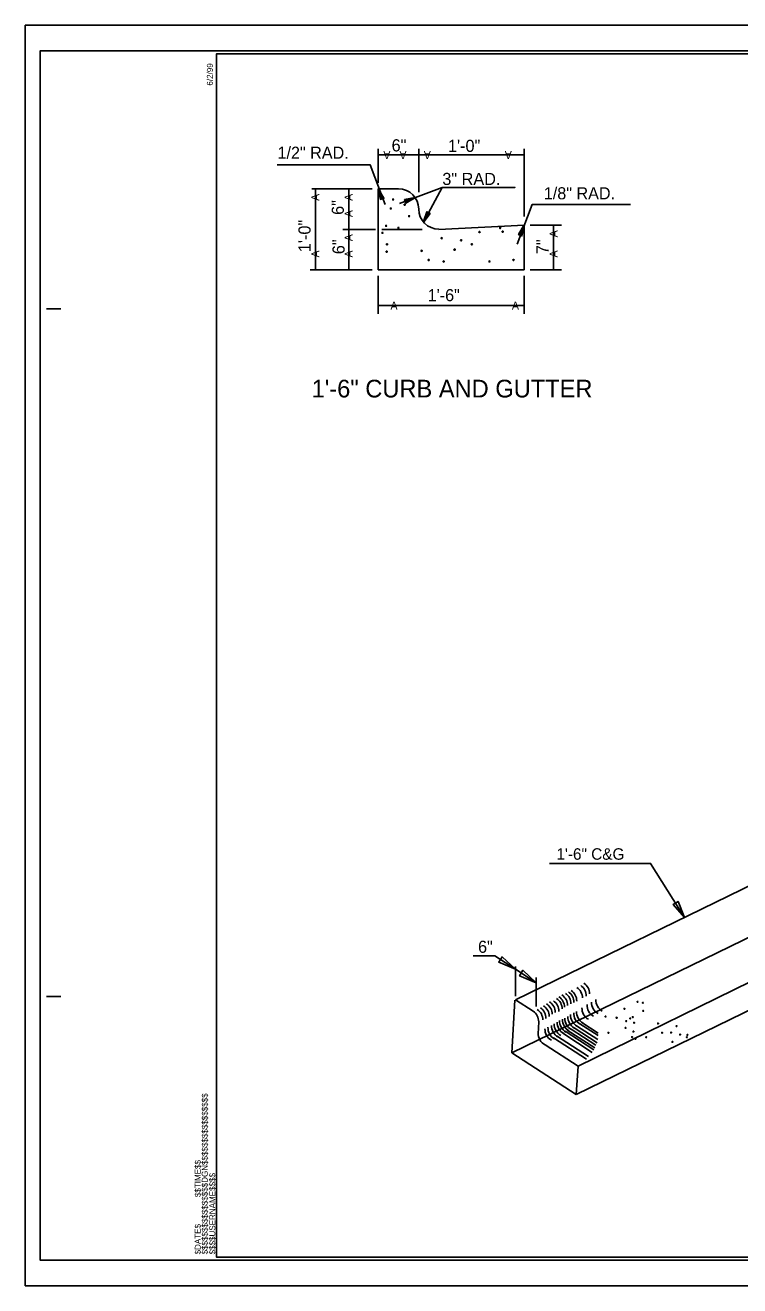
# Model space of a CAD drawing. Extents: x 1252282 to 1252460, y 733735 to 733845.
# Drawn here: x 1252282.2 to 1252344.6, y 733734.5 to 733844.5 of the extents above; entities that cross this region are included whole.
import ezdxf

# ---------------------------------------------------------------- set-up
doc = ezdxf.new("R2010")
doc.units = 0
for name, color, linetype in [('Default', 7, 'Continuous'), ('Old_Level_2', 7, 'Continuous'), ('Old_Level_23', 7, 'Continuous'), ('Old_Level_3', 7, 'Continuous'), ('Sheet Block System Information CELL', 7, 'Continuous'), ('Sheet Cutting Line CELL', 7, 'Continuous'), ('Sheet Plot Border Inside CELL', 7, 'Continuous'), ('Sheet Plot Border Outside CELL', 7, 'Continuous'), ('Sheet Typical CELL', 7, 'Continuous')]:
    doc.layers.add(name, color=color, linetype=linetype)

msp = doc.modelspace()

# ---------------------------------------------------------------- linework, layer by layer
at = {"layer": 'Default'}
for p, q in [((1252351.16, 733772.21), (1252325, 733759.45)), ((1252350.92, 733767.63), (1252324.68, 733754.83)), ((1252356.6, 733766.46), (1252330.45, 733753.68)), ((1252330.28, 733751.19), (1252356.52, 733763.99)), ((1252324.98, 733759.78), (1252324.98, 733762.37)), ((1252324.98, 733762.12), (1252326.79, 733760.94)), ((1252326.79, 733758.87), (1252326.79, 733761.41)), ((1252324.68, 733754.83), (1252324.93, 733759.43)), ((1252325, 733759.45), (1252326.53, 733758.46)), ((1252327.01, 733757.55), (1252326.96, 733756.5)), ((1252330.6, 733757.36), (1252332.2, 733756.33)), ((1252330.77, 733757.48), (1252332.21, 733756.54)), ((1252328.3, 733756.14), (1252331.18, 733754.27)), ((1252328.57, 733756.31), (1252331.37, 733754.5)), ((1252329.11, 733756.55), (1252331.69, 733754.87)), ((1252329.32, 733756.72), (1252331.82, 733755.1)), ((1252329.51, 733756.82), (1252331.9, 733755.26)), ((1252329.85, 733756.89), (1252332.01, 733755.49)), ((1252330.1, 733757.02), (1252332.12, 733755.71)), ((1252330.31, 733757.19), (1252332.17, 733755.99)), ((1252327.58, 733755.54), (1252330.45, 733753.68)), ((1252330.28, 733751.19), (1252324.68, 733754.83)), ((1252330.45, 733753.68), (1252330.28, 733751.19))]:
    msp.add_line(p, q, dxfattribs=at)
for points in [[(1252327.97, 733771.36), (1252336.78, 733771.36), (1252339.75, 733766.64)], [(1252321.29, 733763.3), (1252323.17, 733763.3), (1252324.98, 733762.12)]]:
    msp.add_lwpolyline(points, dxfattribs=at)
msp.add_lwpolyline([(1252339.75, 733766.64), (1252338.74, 733767.76), (1252339.18, 733768.04)], close=True, dxfattribs=at)
for centre in [(1252334.5, 733758.68), (1252335.65, 733759.29), (1252336.11, 733759.2), (1252336.14, 733758.49), (1252332.85, 733757.99), (1252333.82, 733757.89), (1252334.66, 733757.6), (1252335, 733757.83), (1252335.22, 733757.95), (1252335.34, 733757.45), (1252337.43, 733757.39), (1252339.05, 733757.16), (1252333.1, 733756.58), (1252334.6, 733757), (1252335.16, 733756.21), (1252335.28, 733756.69), (1252335.45, 733756.06), (1252336.4, 733756.19), (1252337.78, 733756.58), (1252338.57, 733756.6), (1252339.36, 733756.42), (1252339.95, 733756.19), (1252340, 733756.4), (1252338.69, 733755.78)]:
    msp.add_circle(centre, 0.0425, dxfattribs=at)
for centre, start, end in [((1252329.74, 733759.63), 359.5174, 56.4255), ((1252330.08, 733759.79), 359.5174, 56.4255), ((1252330.36, 733759.99), 359.5174, 56.4255), ((1252327.97, 733758.67), 359.5174, 56.4255), ((1252328.17, 733758.82), 359.5174, 56.4255), ((1252328.44, 733758.97), 359.5174, 56.4255), ((1252328.74, 733759.11), 359.5174, 56.4255), ((1252329, 733759.24), 359.5174, 56.4255), ((1252329.24, 733759.36), 359.5174, 56.4255), ((1252333.09, 733759.43), 177.4498, 241.2122), ((1252325.92, 733757.55), 359.5174, 56.4255), ((1252326.28, 733757.71), 359.5174, 56.4255), ((1252326.56, 733757.84), 359.5174, 56.4255), ((1252326.84, 733758.02), 359.5174, 56.4255), ((1252327.1, 733758.2), 359.5174, 56.4255), ((1252327.36, 733758.37), 359.5174, 56.4255), ((1252327.69, 733758.46), 359.5174, 56.4255), ((1252331.16, 733758.28), 177.4498, 241.2122), ((1252331.4, 733758.39), 177.4498, 241.2122), ((1252331.88, 733758.71), 177.4498, 241.2122), ((1252332.32, 733758.99), 177.4498, 241.2122), ((1252332.72, 733759.21), 177.4498, 241.2122), ((1252329.22, 733757.17), 177.4498, 241.2122), ((1252329.46, 733757.31), 177.4498, 241.2122), ((1252329.72, 733757.47), 177.4498, 241.2122), ((1252329.92, 733757.6), 177.4498, 241.2122), ((1252330.18, 733757.71), 177.4498, 241.2122), ((1252330.39, 733757.82), 177.4498, 241.2122), ((1252330.65, 733757.95), 177.4498, 241.2122), ((1252330.88, 733758.12), 177.4498, 241.2122), ((1252328.05, 733756.52), 177.4498, 244.614), ((1252328.65, 733756.89), 177.4498, 241.2122), ((1252328.91, 733757.01), 177.4498, 241.2122)]:
    msp.add_arc(centre, 1.09, start, end, dxfattribs=at)
at = {"layer": 'Old_Level_2'}
for p, q in [((1252313.01, 733830.23), (1252313.5, 733829.41)), ((1252313.01, 733830.23), (1252313.19, 733829.29)), ((1252313.19, 733829.29), (1252313.5, 733829.41)), ((1252316.24, 733829.46), (1252315.3, 733829.28)), ((1252315.3, 733829.28), (1252315.42, 733828.96)), ((1252316.24, 733829.46), (1252315.42, 733828.96)), ((1252316.95, 733827.31), (1252317.25, 733828.22)), ((1252316.95, 733827.31), (1252317.54, 733828.06)), ((1252317.54, 733828.06), (1252317.25, 733828.22)), ((1252325.73, 733827.05), (1252325.25, 733826.24)), ((1252325.73, 733827.05), (1252325.55, 733826.11)), ((1252325.55, 733826.11), (1252325.25, 733826.24))]:
    msp.add_line(p, q, dxfattribs=at)
for points in [[(1252313.35, 733829.36), (1252313.02, 733830.2), (1252313.27, 733829.32), (1252313.02, 733830.21), (1252313.44, 733829.38), (1252313.03, 733830.2), (1252313.39, 733829.38), (1252313.03, 733830.2), (1252313.31, 733829.34), (1252313.03, 733830.2), (1252313.23, 733829.31), (1252313.03, 733830.2), (1252313.21, 733829.3), (1252313.03, 733830.2), (1252313.33, 733829.34), (1252313.03, 733830.18), (1252313.47, 733829.39), (1252313.03, 733830.19), (1252313.42, 733829.38), (1252313.06, 733830.12), (1252313.38, 733829.36), (1252313.03, 733830.19), (1252313.37, 733829.36), (1252313.03, 733830.18), (1252313.26, 733829.32), (1252313.04, 733830.17), (1252313.29, 733829.33), (1252313.03, 733830.17), (1252313.45, 733829.39), (1252313.03, 733830.19), (1252313.5, 733829.41), (1252313.03, 733830.17), (1252313.5, 733829.41), (1252313.04, 733830.19), (1252313.18, 733829.96), (1252313.05, 733830.17), (1252313.45, 733829.38), (1252313.03, 733830.17), (1252313.2, 733829.3), (1252313.03, 733830.15), (1252313.19, 733829.3), (1252313.02, 733830.21), (1252313.24, 733829.31), (1252313.05, 733830.16), (1252313.32, 733829.34), (1252313.04, 733830.17), (1252313.3, 733829.34), (1252313.05, 733830.15), (1252313.41, 733829.38), (1252313.03, 733830.19), (1252313.48, 733829.41), (1252313.03, 733830.19), (1252313.22, 733829.3), (1252313.03, 733830.19), (1252313.26, 733829.31), (1252313.03, 733830.17), (1252313.34, 733829.35), (1252313.03, 733830.17), (1252313.38, 733829.36), (1252313.03, 733830.18), (1252313.4, 733829.38), (1252313.03, 733830.18), (1252313.43, 733829.38), (1252313.03, 733830.19), (1252313.46, 733829.41), (1252313.03, 733830.19), (1252313.45, 733829.38), (1252313.03, 733830.19), (1252313.48, 733829.41), (1252313.03, 733830.18), (1252313.32, 733829.34), (1252313.03, 733830.2), (1252313.35, 733829.36), (1252313.03, 733830.2), (1252313.29, 733829.34), (1252313.03, 733830.19), (1252313.28, 733829.32), (1252313.03, 733830.17), (1252313.25, 733829.31), (1252313.03, 733830.19), (1252313.22, 733829.3), (1252313.06, 733830.03), (1252313.21, 733829.3), (1252313.11, 733829.81), (1252313.2, 733829.3), (1252313.15, 733829.75), (1252313.27, 733829.32), (1252313.16, 733829.7), (1252313.38, 733829.36), (1252313.13, 733829.94), (1252313.4, 733829.38), (1252313.15, 733829.87), (1252313.39, 733829.36), (1252313.19, 733829.79), (1252313.35, 733829.35), (1252313.2, 733829.71), (1252313.34, 733829.35), (1252313.13, 733829.97), (1252313.43, 733829.38), (1252313.19, 733829.85), (1252313.43, 733829.38)], [(1252315.37, 733829.11), (1252316.21, 733829.45), (1252315.34, 733829.19), (1252316.23, 733829.45), (1252315.4, 733829.02), (1252316.21, 733829.44), (1252315.38, 733829.08), (1252316.21, 733829.44), (1252315.35, 733829.15), (1252316.21, 733829.44), (1252315.32, 733829.23), (1252316.21, 733829.44), (1252315.31, 733829.25), (1252316.21, 733829.44), (1252315.35, 733829.14), (1252316.18, 733829.44), (1252315.41, 733828.98), (1252316.2, 733829.43), (1252315.39, 733829.04), (1252316.13, 733829.41), (1252315.38, 733829.09), (1252316.2, 733829.43), (1252315.37, 733829.1), (1252316.18, 733829.43), (1252315.34, 733829.2), (1252316.18, 733829.43), (1252315.34, 733829.17), (1252316.18, 733829.43), (1252315.41, 733829.01), (1252316.2, 733829.44), (1252315.42, 733828.97), (1252316.18, 733829.43), (1252315.42, 733828.97), (1252316.2, 733829.43), (1252315.97, 733829.29), (1252316.18, 733829.41), (1252315.4, 733829.02), (1252316.18, 733829.43), (1252315.31, 733829.27), (1252316.16, 733829.43), (1252315.31, 733829.27), (1252316.23, 733829.45), (1252315.33, 733829.23), (1252316.17, 733829.41), (1252315.35, 733829.14), (1252316.18, 733829.43), (1252315.35, 733829.16), (1252316.16, 733829.41), (1252315.39, 733829.06), (1252316.2, 733829.43), (1252315.42, 733828.98), (1252316.2, 733829.43), (1252315.31, 733829.23), (1252316.2, 733829.43), (1252315.33, 733829.2), (1252316.18, 733829.43), (1252315.36, 733829.12), (1252316.18, 733829.43), (1252315.38, 733829.09), (1252316.18, 733829.43), (1252315.39, 733829.06), (1252316.18, 733829.43), (1252315.4, 733829.04), (1252316.2, 733829.44), (1252315.41, 733829), (1252316.2, 733829.43), (1252315.4, 733829.01), (1252316.2, 733829.43), (1252315.41, 733828.98), (1252316.18, 733829.43), (1252315.35, 733829.15), (1252316.21, 733829.44), (1252315.37, 733829.11), (1252316.21, 733829.44), (1252315.35, 733829.17), (1252316.2, 733829.44), (1252315.34, 733829.18), (1252316.18, 733829.43), (1252315.33, 733829.22), (1252316.2, 733829.44), (1252315.31, 733829.23), (1252316.04, 733829.41), (1252315.31, 733829.26), (1252315.81, 733829.35), (1252315.31, 733829.27), (1252315.76, 733829.32), (1252315.34, 733829.19), (1252315.72, 733829.3), (1252315.38, 733829.08), (1252315.95, 733829.33), (1252315.38, 733829.06), (1252315.88, 733829.31), (1252315.38, 733829.08), (1252315.8, 733829.28), (1252315.36, 733829.11), (1252315.73, 733829.27), (1252315.36, 733829.13), (1252315.99, 733829.33), (1252315.39, 733829.04), (1252315.86, 733829.27), (1252315.4, 733829.02)], [(1252317.39, 733828.14), (1252316.96, 733827.33), (1252317.45, 733828.11), (1252316.96, 733827.33), (1252317.31, 733828.19), (1252316.96, 733827.34), (1252317.34, 733828.16), (1252316.96, 733827.33), (1252317.42, 733828.12), (1252316.96, 733827.33), (1252317.5, 733828.08), (1252316.96, 733827.33), (1252317.51, 733828.07), (1252316.96, 733827.34), (1252317.41, 733828.14), (1252316.97, 733827.36), (1252317.27, 733828.2), (1252316.97, 733827.36), (1252317.32, 733828.18), (1252317, 733827.42), (1252317.36, 733828.16), (1252316.97, 733827.36), (1252317.37, 733828.14), (1252316.98, 733827.36), (1252317.47, 733828.09), (1252316.98, 733827.37), (1252317.45, 733828.11), (1252316.99, 733827.37), (1252317.29, 733828.2), (1252316.97, 733827.35), (1252317.26, 733828.21), (1252316.98, 733827.37), (1252317.26, 733828.22), (1252316.96, 733827.36), (1252317.05, 733827.62), (1252316.98, 733827.38), (1252317.31, 733828.19), (1252316.99, 733827.37), (1252317.53, 733828.06), (1252317, 733827.37), (1252317.53, 733828.06), (1252316.96, 733827.33), (1252317.48, 733828.08), (1252316.99, 733827.38), (1252317.41, 733828.12), (1252316.99, 733827.37), (1252317.43, 733828.12), (1252316.99, 733827.4), (1252317.33, 733828.17), (1252316.96, 733827.35), (1252317.26, 733828.21), (1252316.96, 733827.35), (1252317.51, 733828.07), (1252316.97, 733827.36), (1252317.47, 733828.09), (1252316.98, 733827.37), (1252317.39, 733828.14), (1252316.98, 733827.37), (1252317.37, 733828.16), (1252316.98, 733827.36), (1252317.34, 733828.17), (1252316.98, 733827.36), (1252317.32, 733828.18), (1252316.98, 733827.35), (1252317.28, 733828.2), (1252316.97, 733827.36), (1252317.3, 733828.2), (1252316.96, 733827.35), (1252317.26, 733828.21), (1252316.98, 733827.36), (1252317.41, 733828.12), (1252316.96, 733827.33), (1252317.38, 733828.14), (1252316.96, 733827.34), (1252317.44, 733828.11), (1252316.96, 733827.34), (1252317.45, 733828.11), (1252316.98, 733827.37), (1252317.48, 733828.09), (1252316.97, 733827.35), (1252317.51, 733828.07), (1252317.06, 733827.49), (1252317.52, 733828.07), (1252317.2, 733827.67), (1252317.53, 733828.07), (1252317.22, 733827.73), (1252317.47, 733828.09), (1252317.25, 733827.77), (1252317.35, 733828.16), (1252317.08, 733827.58), (1252317.34, 733828.17), (1252317.13, 733827.66), (1252317.35, 733828.16), (1252317.17, 733827.73), (1252317.39, 733828.14), (1252317.22, 733827.8), (1252317.4, 733828.14), (1252317.06, 733827.56), (1252317.32, 733828.19), (1252317.11, 733827.69), (1252317.31, 733828.19)], [(1252325.39, 733826.18), (1252325.73, 733827.03), (1252325.47, 733826.14), (1252325.73, 733827.03), (1252325.31, 733826.21), (1252325.72, 733827.02), (1252325.35, 733826.19), (1252325.72, 733827.03), (1252325.44, 733826.16), (1252325.72, 733827.03), (1252325.51, 733826.13), (1252325.72, 733827.03), (1252325.54, 733826.12), (1252325.72, 733827.03), (1252325.41, 733826.17), (1252325.72, 733827), (1252325.28, 733826.21), (1252325.71, 733827.01), (1252325.32, 733826.21), (1252325.69, 733826.95), (1252325.36, 733826.18), (1252325.71, 733827.01), (1252325.38, 733826.18), (1252325.71, 733827), (1252325.48, 733826.14), (1252325.7, 733826.99), (1252325.46, 733826.15), (1252325.71, 733826.99), (1252325.29, 733826.21), (1252325.72, 733827.01), (1252325.25, 733826.24), (1252325.71, 733827), (1252325.25, 733826.24), (1252325.7, 733827.01), (1252325.57, 733826.77), (1252325.7, 733826.99), (1252325.3, 733826.21), (1252325.71, 733826.99), (1252325.54, 733826.12), (1252325.71, 733826.97), (1252325.55, 733826.12), (1252325.73, 733827.03), (1252325.5, 733826.14), (1252325.7, 733826.98), (1252325.42, 733826.17), (1252325.7, 733826.99), (1252325.44, 733826.16), (1252325.7, 733826.97), (1252325.34, 733826.21), (1252325.71, 733827.01), (1252325.26, 733826.24), (1252325.71, 733827.01), (1252325.52, 733826.12), (1252325.71, 733827.01), (1252325.47, 733826.14), (1252325.71, 733826.99), (1252325.4, 733826.17), (1252325.71, 733827), (1252325.37, 733826.18), (1252325.71, 733827), (1252325.34, 733826.19), (1252325.71, 733827), (1252325.31, 733826.21), (1252325.72, 733827.01), (1252325.28, 733826.23), (1252325.71, 733827.01), (1252325.29, 733826.21), (1252325.71, 733827.01), (1252325.26, 733826.23), (1252325.71, 733827), (1252325.42, 733826.17), (1252325.72, 733827.03), (1252325.39, 733826.18), (1252325.72, 733827.02), (1252325.45, 733826.16), (1252325.72, 733827.01), (1252325.47, 733826.14), (1252325.71, 733827), (1252325.5, 733826.14), (1252325.72, 733827.01), (1252325.52, 733826.12), (1252325.68, 733826.85), (1252325.54, 733826.12), (1252325.63, 733826.63), (1252325.54, 733826.12), (1252325.6, 733826.56), (1252325.47, 733826.14), (1252325.58, 733826.52), (1252325.36, 733826.18), (1252325.61, 733826.77), (1252325.34, 733826.19), (1252325.59, 733826.69), (1252325.35, 733826.18), (1252325.56, 733826.62), (1252325.39, 733826.17), (1252325.54, 733826.53), (1252325.41, 733826.17), (1252325.61, 733826.8), (1252325.31, 733826.21), (1252325.55, 733826.68), (1252325.31, 733826.21)]]:
    msp.add_lwpolyline(points, dxfattribs=at)
for points in [[(1252324.98, 733762.12), (1252323.52, 733762.74), (1252323.82, 733763.2)], [(1252326.79, 733760.94), (1252325.34, 733761.56), (1252325.64, 733762.03)]]:
    msp.add_lwpolyline(points, close=True, dxfattribs=at)
at = {"layer": 'Old_Level_23'}
for p, q in [((1252313.01, 733830.76), (1252313.01, 733833.71)), ((1252316.55, 733833.18), (1252313.01, 733833.18)), ((1252316.55, 733829.92), (1252316.55, 733833.71)), ((1252325.73, 733833.18), (1252316.55, 733833.18)), ((1252325.73, 733827.82), (1252325.73, 733833.71)), ((1252312.48, 733830.23), (1252307.21, 733830.23)), ((1252307.53, 733823.17), (1252307.53, 733830.23)), ((1252310.44, 733826.69), (1252310.44, 733830.23)), ((1252312.77, 733826.69), (1252309.9, 733826.69)), ((1252310.44, 733823.17), (1252310.44, 733826.69)), ((1252316.85, 733826.69), (1252313.32, 733826.69)), ((1252326.26, 733827.05), (1252328.99, 733827.05)), ((1252328.31, 733823.17), (1252328.31, 733827.05)), ((1252312.48, 733823.17), (1252307.05, 733823.17)), ((1252313.01, 733822.64), (1252313.01, 733819.31)), ((1252325.73, 733822.64), (1252325.73, 733819.31)), ((1252326.26, 733823.17), (1252328.99, 733823.17)), ((1252313.01, 733820.03), (1252325.73, 733820.03))]:
    msp.add_line(p, q, dxfattribs=at)
for points in [[(1252313.6, 733828.85), (1252312.29, 733832.32), (1252304.19, 733832.32)], [(1252316.95, 733827.31), (1252318.58, 733830.35), (1252324.94, 733830.35), (1252318.58, 733830.35), (1252314.86, 733828.94)], [(1252325.12, 733825.39), (1252326.43, 733828.85), (1252335.02, 733828.85)]]:
    msp.add_lwpolyline(points, dxfattribs=at)
at = {"layer": 'Old_Level_3'}
msp.add_lwpolyline([(1252314.78, 733830.23), (1252313.01, 733830.23), (1252313.01, 733823.17), (1252325.73, 733823.17), (1252325.73, 733827.05), (1252318.3, 733826.69)], dxfattribs=at)
for centre, radius in [((1252314.31, 733829.3), 0.0517), ((1252315.31, 733828.84), 0.0517), ((1252314.1, 733828.51), 0.0517), ((1252315.7, 733827.84), 0.0517), ((1252313.69, 733826.99), 0.0517), ((1252314.77, 733826.82), 0.0548), ((1252321.84, 733826.46), 0.0517), ((1252323.65, 733826.8), 0.0517), ((1252323.87, 733826.49), 0.0517), ((1252313.38, 733826.38), 0.0517), ((1252313.77, 733825.38), 0.0517), ((1252318.54, 733825.92), 0.0517), ((1252320.24, 733825.73), 0.0561), ((1252321.17, 733825.38), 0.0517), ((1252313.74, 733824.74), 0.0517), ((1252316.8, 733824.81), 0.0517), ((1252319.67, 733824.92), 0.0556), ((1252317.4, 733824.01), 0.0517), ((1252318.71, 733823.88), 0.0517), ((1252322.72, 733823.89), 0.0517), ((1252324.81, 733824.01), 0.0517)]:
    msp.add_circle(centre, radius, dxfattribs=at)
for centre, start, end in [((1252314.78, 733828.46), 0, 90), ((1252318.3, 733828.46), 180, 270)]:
    msp.add_arc(centre, 1.76, start, end, dxfattribs=at)
at = {"layer": 'Sheet Block System Information CELL'}
msp.add_line((1252298.88, 733737), (1252298.88, 733737), dxfattribs=at)
msp.add_line((1252298.88, 733737), (1252298.88, 733737), dxfattribs=at)
at = {"layer": 'Sheet Cutting Line CELL'}
for p, q in [((1252450.58, 733844.5), (1252282.18, 733844.5)), ((1252282.18, 733844.5), (1252282.18, 733734.5)), ((1252282.18, 733734.5), (1252450.58, 733734.5))]:
    msp.add_line(p, q, dxfattribs=at)
at = {"layer": 'Sheet Plot Border Inside CELL'}
msp.add_lwpolyline([(1252450.13, 733842.26), (1252283.48, 733842.26), (1252283.48, 733736.75), (1252450.13, 733736.75)], close=True, dxfattribs=at)
at = {"layer": 'Sheet Plot Border Outside CELL'}
msp.add_lwpolyline([(1252450.58, 733844.5), (1252282.18, 733844.5), (1252282.18, 733734.5), (1252450.58, 733734.5)], close=True, dxfattribs=at)
at = {"layer": 'Sheet Typical CELL'}
for p, q in [((1252284.03, 733819.75), (1252285.28, 733819.75)), ((1252284.03, 733759.75), (1252285.28, 733759.75)), ((1252298.88, 733737), (1252298.88, 733737)), ((1252298.88, 733737), (1252298.88, 733737)), ((1252298.88, 733737), (1252298.88, 733737)), ((1252298.88, 733737), (1252298.88, 733737)), ((1252298.88, 733737), (1252298.88, 733737)), ((1252298.88, 733737), (1252298.88, 733737))]:
    msp.add_line(p, q, dxfattribs=at)
msp.add_lwpolyline([(1252448.88, 733842), (1252298.88, 733842), (1252298.88, 733737), (1252448.88, 733737)], close=True, dxfattribs=at)
msp.add_lwpolyline([(1252302.63, 733737), (1252302.63, 733737)], dxfattribs=at)

# ---------------------------------------------------------------- texts
at = {"layer": 'Default'}
for s, height, p in [('1\'-6" C&G', 1.001, (1252328.56, 733771.68)), ('6"', 1.054, (1252321.72, 733763.56))]:
    msp.add_text(s, height=height, dxfattribs=at).set_placement(p)
at = {"layer": 'Old_Level_23'}
for s, height, p in [('6"', 1.06, (1252314.17, 733833.49)), ('1\'-0"', 1.06, (1252319.09, 733833.45)), ('1/2" RAD.', 1.054, (1252304.21, 733832.85)), ('3" RAD.', 1.06, (1252318.6, 733830.56)), ('1/8" RAD.', 1.054, (1252327.46, 733829.31)), ('1\'-6"', 1.054, (1252317.32, 733820.42)), ('A', 0.698, (1252314.07, 733819.68)), ('A', 0.698, (1252324.67, 733819.68)), ('1\'-6" CURB AND GUTTER', 1.5433, (1252307.19, 733812.02))]:
    msp.add_text(s, height=height, dxfattribs=at).set_placement(p)
for s, height, rotation, p in [('A', 0.698, 180, (1252314.07, 733833.53)), ('A', 0.698, 180, (1252315.48, 733833.53)), ('A', 0.698, 180, (1252317.6, 733833.53)), ('A', 0.698, 180, (1252324.67, 733833.53)), ('A', 0.698, 90, (1252307.87, 733829.17)), ('6"', 1.06, 90, (1252310, 733827.95)), ('A', 0.698, 90, (1252310.78, 733829.17)), ('A', 0.698, 90, (1252310.78, 733827.75)), ('1\'-0"', 1.06, 90, (1252307.1, 733824.7)), ('A', 0.698, 90, (1252328.66, 733825.99)), ('6"', 1.06, 90, (1252310.07, 733824.52)), ('A', 0.698, 90, (1252310.78, 733825.65)), ('7"', 1.054, 90, (1252327.87, 733824.53)), ('A', 0.698, 90, (1252307.87, 733824.23)), ('A', 0.698, 90, (1252310.78, 733824.23)), ('A', 0.698, 90, (1252328.66, 733824.23))]:
    msp.add_text(s, height=height, rotation=rotation, dxfattribs=at).set_placement(p)
at = {"layer": 'Sheet Block System Information CELL'}
for s, p in [('$$$$$$$$$$$$$$$$DGN$$$$$$$$$$$$$$$$', (1252298.12, 733737.24)), ('$$TIME$$', (1252297.51, 733742.24)), ('$$$$USERNAME$$$$', (1252298.78, 733737.24)), ('$DATE$', (1252297.51, 733737.24))]:
    msp.add_text(s, height=0.525, rotation=90, dxfattribs=at).set_placement(p)
at = {"layer": 'Sheet Typical CELL'}
msp.add_text('6/2/99', height=0.525, rotation=90, dxfattribs=at).set_placement((1252298.57, 733839.23))

doc.saveas('drawing.dxf')
